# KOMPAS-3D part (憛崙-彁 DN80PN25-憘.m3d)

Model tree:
1. Объединить компоненты:1  (labels: СЕНС-ПР DN80PN25)
2. Эскиз:1
3. Операция выдавливания:1
     Расстояние 1 = 14; Расстояние 2 = 20.75
4. Фаска:1
     Угол = 45; Длина 1 = 2; Длина 2 = 2

Referenced files in D:\Савин\!СЕНСОР\3D для заказчика\!Новый перечень\СЕНС-ПР\1. СЕНС-ПР\DN80\: СЕНС-ПР DN80PN25.a3d
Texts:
  СЕНС-ПР DN80PN25-СВ
  ООО НПП Сенсор
  СЕНС-ПР DN80PN25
